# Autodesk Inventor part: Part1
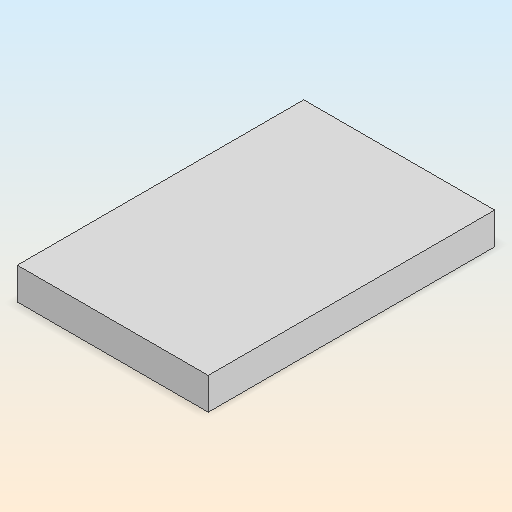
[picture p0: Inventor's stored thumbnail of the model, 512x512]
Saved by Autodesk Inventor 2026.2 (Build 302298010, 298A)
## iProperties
Created: 2026-02
Part Number: Part1
Material: Generic
Document SubType Name: Modeling
Designer: LSB
Density: 1 g/cm^3
Appearance: Default
Author: LSB
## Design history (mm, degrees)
sketch "Sketch1"
  geometry: L1 (0, 0)-(1219.2, 0); L2 (1219.2, 0)-(1219.2, 203.2); L3 (1219.2, 203.2)-(0, 203.2); L4 (0, 203.2)-(0, 0)
  constraints: 8 end point, 2 parallel, 1 horizontal, 1 perpendicular
  dimensions: "d0" = 1219.2 distance of L3.end L2.end; "d1" = 203.2 distance of L2.end L1.end
extrude "Extrusion1" new body sketch "Sketch1" distance "d2" = 1828.8; taper "d3" = 0 deg
body "Solid1"
